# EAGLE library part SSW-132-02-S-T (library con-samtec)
THROUGH-HOLE .025" SQ POST SOCKET Source: Samtec SSW.pdf
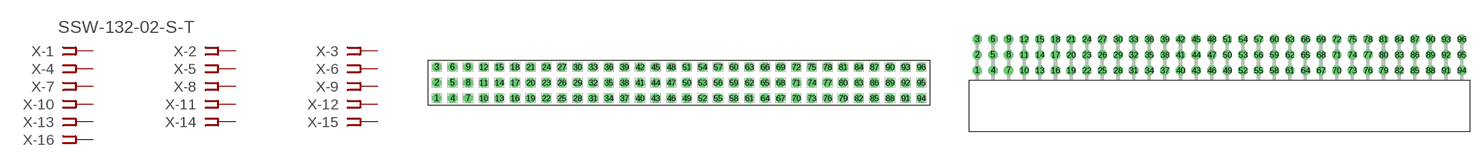
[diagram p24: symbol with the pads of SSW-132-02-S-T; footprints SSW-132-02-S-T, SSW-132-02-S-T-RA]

Designator prefix X; gates -1=FPINV -2=FPIN -3=FPIN -4=FPIN -5=FPIN -6=FPIN -7=FPIN -8=FPIN -9=FPIN -10=FPIN -11=FPIN -12=FPIN -13=FPIN -14=FPIN -15=FPIN -16=FPIN -17=FPIN -18=FPIN -19=FPIN -20=FPIN -21=FPIN -22=FPIN -23=FPIN -24=FPIN -25=FPIN -26=FPIN -27=FPIN -28=FPIN -29=FPIN -30=FPIN -31=FPIN -32=FPIN -33=FPIN -34=FPIN -35=FPIN -36=FPIN -37=FPIN -38=FPIN -39=FPIN -40=FPIN -41=FPIN -42=FPIN -43=FPIN -44=FPIN -45=FPIN -46=FPIN -47=FPIN -48=FPIN -49=FPIN -50=FPIN -51=FPIN -52=FPIN -53=FPIN -54=FPIN -55=FPIN -56=FPIN -57=FPIN -58=FPIN -59=FPIN -60=FPIN -61=FPIN -62=FPIN -63=FPIN -64=FPIN -65=FPIN -66=FPIN -67=FPIN -68=FPIN -69=FPIN -70=FPIN -71=FPIN -72=FPIN -73=FPIN -74=FPIN -75=FPIN -76=FPIN -77=FPIN -78=FPIN -79=FPIN -80=FPIN -81=FPIN -82=FPIN -83=FPIN -84=FPIN -85=FPIN -86=FPIN -87=FPIN -88=FPIN -89=FPIN -90=FPIN -91=FPIN -92=FPIN -93=FPIN -94=FPIN -95=FPIN -96=FPIN

## SSW-132-02-S-T (MPN: SSW-132-02-S-T; OC_FARNELL: unknown; OC_NEWARK: 83P0342)  [SSW-132-02-S-T]
1  -1:1  pas
2  -2:1  pas
3  -3:1  pas
4  -4:1  pas
5  -5:1  pas
6  -6:1  pas
7  -7:1  pas
8  -8:1  pas
9  -9:1  pas
10  -10:1  pas
11  -11:1  pas
12  -12:1  pas
13  -13:1  pas
14  -14:1  pas
15  -15:1  pas
16  -16:1  pas
17  -17:1  pas
18  -18:1  pas
19  -19:1  pas
20  -20:1  pas
21  -21:1  pas
22  -22:1  pas
23  -23:1  pas
24  -24:1  pas
25  -25:1  pas
26  -26:1  pas
27  -27:1  pas
28  -28:1  pas
29  -29:1  pas
30  -30:1  pas
31  -31:1  pas
32  -32:1  pas
33  -33:1  pas
34  -34:1  pas
35  -35:1  pas
36  -36:1  pas
37  -37:1  pas
38  -38:1  pas
39  -39:1  pas
40  -40:1  pas
41  -41:1  pas
42  -42:1  pas
43  -43:1  pas
44  -44:1  pas
45  -45:1  pas
46  -46:1  pas
47  -47:1  pas
48  -48:1  pas
49  -49:1  pas
50  -50:1  pas
51  -51:1  pas
52  -52:1  pas
53  -53:1  pas
54  -54:1  pas
55  -55:1  pas
56  -56:1  pas
57  -57:1  pas
58  -58:1  pas
59  -59:1  pas
60  -60:1  pas
61  -61:1  pas
62  -62:1  pas
63  -63:1  pas
64  -64:1  pas
65  -65:1  pas
66  -66:1  pas
67  -67:1  pas
68  -68:1  pas
69  -69:1  pas
70  -70:1  pas
71  -71:1  pas
72  -72:1  pas
73  -73:1  pas
74  -74:1  pas
75  -75:1  pas
76  -76:1  pas
77  -77:1  pas
78  -78:1  pas
79  -79:1  pas
80  -80:1  pas
81  -81:1  pas
82  -82:1  pas
83  -83:1  pas
84  -84:1  pas
85  -85:1  pas
86  -86:1  pas
87  -87:1  pas
88  -88:1  pas
89  -89:1  pas
90  -90:1  pas
91  -91:1  pas
92  -92:1  pas
93  -93:1  pas
94  -94:1  pas
95  -95:1  pas
96  -96:1  pas

## SSW-132-02-S-TRA (MPN: SSW-132-02-S-T-RA; OC_FARNELL: unknown; OC_NEWARK: 83P0343)  [SSW-132-02-S-T-RA]
Pads as for SSW-132-02-S-T

## Footprint SSW-132-02-S-T (pad centres in mm)
THROUGH-HOLE .025" SQ POST SOCKET Source: Samtec SSW.pdf
drill 1 pad 1.5 octagon: 1 -39.37,-2.54; 2 -39.37,0; 3 -39.37,2.54; 4 -36.83,-2.54; 5 -36.83,0; 6 -36.83,2.54; 7 -34.29,-2.54; 8 -34.29,0; 9 -34.29,2.54; 10 -31.75,-2.54; 11 -31.75,0; 12 -31.75,2.54; 13 -29.21,-2.54; 14 -29.21,0; 15 -29.21,2.54; 16 -26.67,-2.54; 17 -26.67,0; 18 -26.67,2.54; 19 -24.13,-2.54; 20 -24.13,0; 21 -24.13,2.54; 22 -21.59,-2.54; 23 -21.59,0; 24 -21.59,2.54; 25 -19.05,-2.54; 26 -19.05,0; 27 -19.05,2.54; 28 -16.51,-2.54; 29 -16.51,0; 30 -16.51,2.54; 31 -13.97,-2.54; 32 -13.97,0; 33 -13.97,2.54; 34 -11.43,-2.54; 35 -11.43,0; 36 -11.43,2.54; 37 -8.89,-2.54; 38 -8.89,0; 39 -8.89,2.54; 40 -6.35,-2.54; 41 -6.35,0; 42 -6.35,2.54; 43 -3.81,-2.54; 44 -3.81,0; 45 -3.81,2.54; 46 -1.27,-2.54; 47 -1.27,0; 48 -1.27,2.54; 49 1.27,-2.54; 50 1.27,0; 51 1.27,2.54; 52 3.81,-2.54; 53 3.81,0; 54 3.81,2.54; 55 6.35,-2.54; 56 6.35,0; 57 6.35,2.54; 58 8.89,-2.54; 59 8.89,0; 60 8.89,2.54; 61 11.43,-2.54; 62 11.43,0; 63 11.43,2.54; 64 13.97,-2.54; 65 13.97,0; 66 13.97,2.54; 67 16.51,-2.54; 68 16.51,0; 69 16.51,2.54; 70 19.05,-2.54; 71 19.05,0; 72 19.05,2.54; 73 21.59,-2.54; 74 21.59,0; 75 21.59,2.54; 76 24.13,-2.54; 77 24.13,0; 78 24.13,2.54; 79 26.67,-2.54; 80 26.67,0; 81 26.67,2.54; 82 29.21,-2.54; 83 29.21,0; 84 29.21,2.54; 85 31.75,-2.54; 86 31.75,0; 87 31.75,2.54; 88 34.29,-2.54; 89 34.29,0; 90 34.29,2.54; 91 36.83,-2.54; 92 36.83,0; 93 36.83,2.54; 94 39.37,-2.54; 95 39.37,0; 96 39.37,2.54

## Footprint SSW-132-02-S-T-RA (pad centres in mm)
THROUGH-HOLE .025" SQ POST SOCKET Source: Samtec SSW.pdf
drill 1 pad 1.5 octagon: 1 -39.37,1.524; 2 -39.37,4.064; 3 -39.37,6.604; 4 -36.83,1.524; 5 -36.83,4.064; 6 -36.83,6.604; 7 -34.29,1.524; 8 -34.29,4.064; 9 -34.29,6.604; 10 -31.75,1.524; 11 -31.75,4.064; 12 -31.75,6.604; 13 -29.21,1.524; 14 -29.21,4.064; 15 -29.21,6.604; 16 -26.67,1.524; 17 -26.67,4.064; 18 -26.67,6.604; 19 -24.13,1.524; 20 -24.13,4.064; 21 -24.13,6.604; 22 -21.59,1.524; 23 -21.59,4.064; 24 -21.59,6.604; 25 -19.05,1.524; 26 -19.05,4.064; 27 -19.05,6.604; 28 -16.51,1.524; 29 -16.51,4.064; 30 -16.51,6.604; 31 -13.97,1.524; 32 -13.97,4.064; 33 -13.97,6.604; 34 -11.43,1.524; 35 -11.43,4.064; 36 -11.43,6.604; 37 -8.89,1.524; 38 -8.89,4.064; 39 -8.89,6.604; 40 -6.35,1.524; 41 -6.35,4.064; 42 -6.35,6.604; 43 -3.81,1.524; 44 -3.81,4.064; 45 -3.81,6.604; 46 -1.27,1.524; 47 -1.27,4.064; 48 -1.27,6.604; 49 1.27,1.524; 50 1.27,4.064; 51 1.27,6.604; 52 3.81,1.524; 53 3.81,4.064; 54 3.81,6.604; 55 6.35,1.524; 56 6.35,4.064; 57 6.35,6.604; 58 8.89,1.524; 59 8.89,4.064; 60 8.89,6.604; 61 11.43,1.524; 62 11.43,4.064; 63 11.43,6.604; 64 13.97,1.524; 65 13.97,4.064; 66 13.97,6.604; 67 16.51,1.524; 68 16.51,4.064; 69 16.51,6.604; 70 19.05,1.524; 71 19.05,4.064; 72 19.05,6.604; 73 21.59,1.524; 74 21.59,4.064; 75 21.59,6.604; 76 24.13,1.524; 77 24.13,4.064; 78 24.13,6.604; 79 26.67,1.524; 80 26.67,4.064; 81 26.67,6.604; 82 29.21,1.524; 83 29.21,4.064; 84 29.21,6.604; 85 31.75,1.524; 86 31.75,4.064; 87 31.75,6.604; 88 34.29,1.524; 89 34.29,4.064; 90 34.29,6.604; 91 36.83,1.524; 92 36.83,4.064; 93 36.83,6.604; 94 39.37,1.524; 95 39.37,4.064; 96 39.37,6.604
